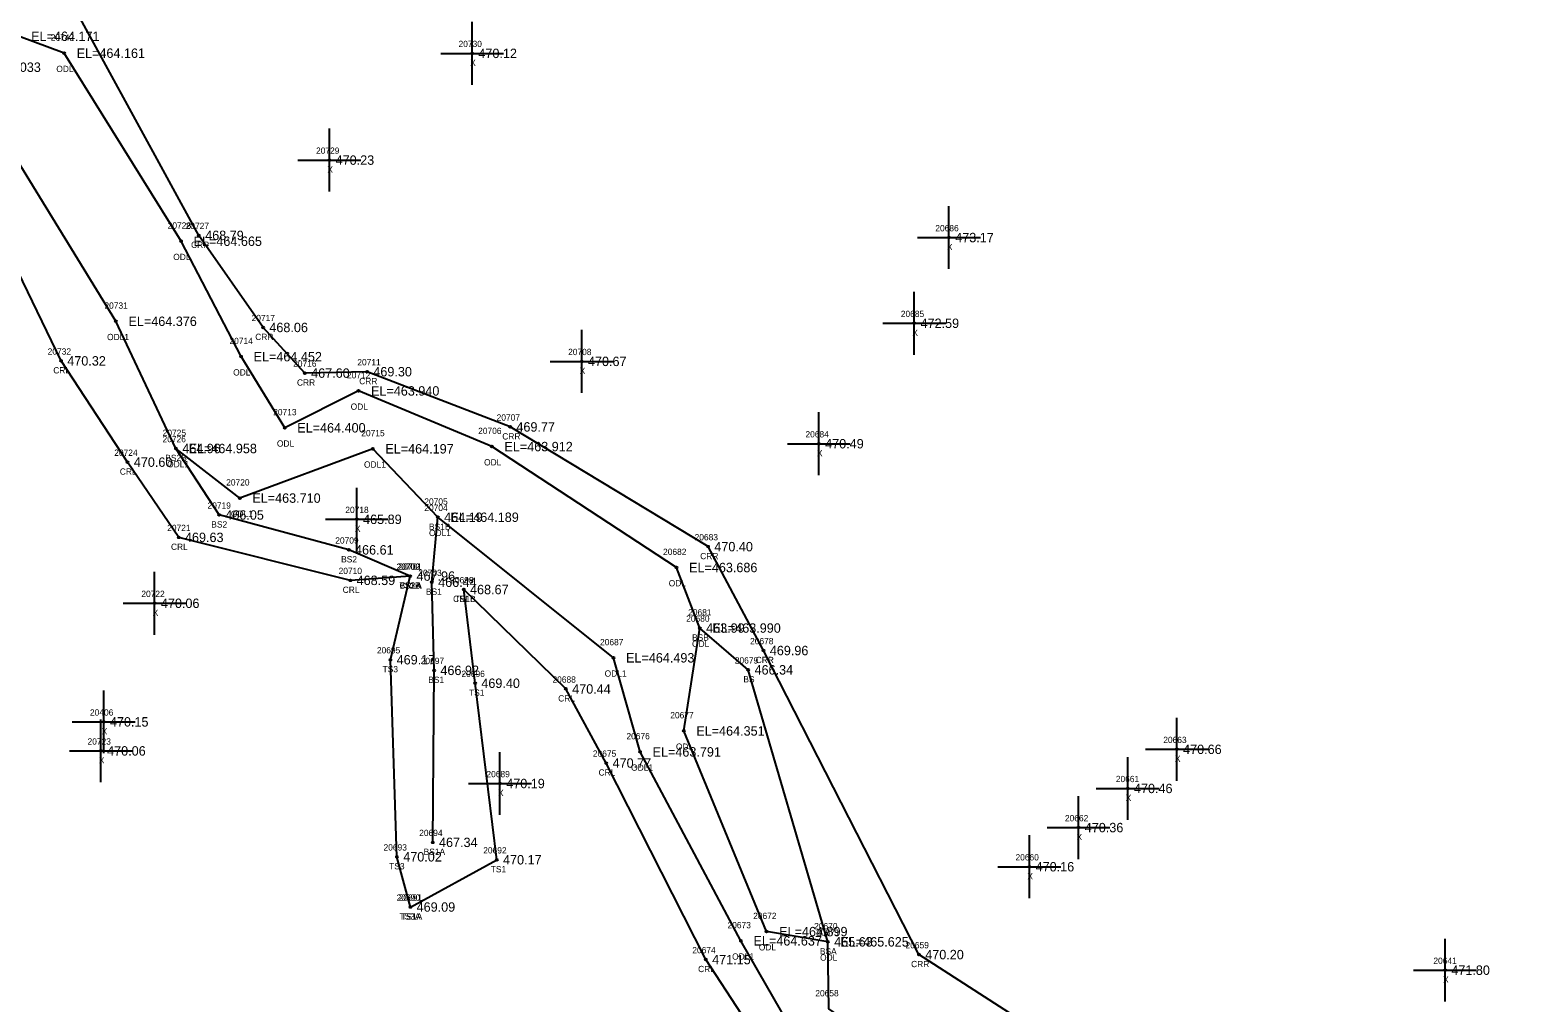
# Model space of a CAD drawing. Extents: x 1741010 to 1742139, y 749382 to 750625.
# Drawn here: x 1741616.4 to 1741856.4, y 749886.5 to 750041.3 of the extents above; entities that cross this region are included whole.
import ezdxf

# ---------------------------------------------------------------- set-up
doc = ezdxf.new("R2010")
doc.units = 0
for name, color, linetype in [('RD_DTM_BkLn2', 7, 'Continuous'), ('RD_DTM_BkLn_txCode', 7, 'Continuous'), ('RD_EX_H2O', 7, 'Continuous'), ('RD_EX_H2O_txCode', 7, 'Continuous'), ('RD_EX_Misc', 7, 'Continuous'), ('RD_EX_Misc_txCode', 7, 'Continuous'), ('RD_EX_TX_H2O_ELEV', 7, 'Continuous'), ('RD_EX_TX_Misc_ELEV', 7, 'Continuous'), ('RD_SMD_Locator', 7, 'Continuous')]:
    doc.layers.add(name, color=color, linetype=linetype)

msp = doc.modelspace()

# ---------------------------------------------------------------- linework, layer by layer
at = {"layer": 'RD_DTM_BkLn2'}
for points in [[(1741676.89, 749954.42), (1741667.11, 749958.59), (1741646.46, 749964.14), (1741639.61, 749974.72)], [(1741680.47, 749912.05), (1741680.7, 749939.42), (1741680.34, 749953.44), (1741681.29, 749963.78)], [(1741676.91, 749901.76), (1741674.78, 749909.75), (1741673.73, 749941.11), (1741676.89, 749954.42)], [(1741676.91, 749901.76), (1741690.66, 749909.28), (1741687.21, 749937.37), (1741685.41, 749952.28)], [(1741743.36, 749896.22), (1741730.69, 749939.5), (1741722.99, 749946.15)]]:
    msp.add_lwpolyline(points, dxfattribs=at)
at = {"layer": 'RD_EX_H2O'}
for points in [[(1742009.73, 749699.92), (1741998.41, 749723.73), (1741963.19, 749743.52), (1741899.78, 749744.87), (1741875.61, 749759.72), (1741846.8, 749796.06), (1741820.86, 749838.72), (1741812.23, 749854.24), (1741798.02, 749868.34), (1741757.86, 749894.19), (1741733.12, 749942.57), (1741724.29, 749959.1), (1741692.79, 749978.15), (1741670.02, 749986.94), (1741660.12, 749986.72), (1741653.47, 749993.98), (1741643.26, 750008.63), (1741623.07, 750045.53)], [(1741979.95, 749694.15), (1741975.81, 749711.2), (1741958.44, 749721.88), (1741894.61, 749726.87), (1741877.76, 749724.44), (1741850.91, 749736.65), (1741828.26, 749780.7), (1741797.14, 749817.35), (1741808.22, 749831.81), (1741810.09, 749840.16), (1741785.92, 749848.46), (1741738.7, 749880.42), (1741729.53, 749896.38), (1741713.46, 749926.44), (1741709.24, 749941.41), (1741681.29, 749963.78), (1741670.93, 749974.67), (1741649.76, 749966.83), (1741639.61, 749974.72), (1741630.05, 749994.96), (1741605.22, 750035.39), (1741604.28, 750042.48)], [(1741997.88, 749696.99), (1741991.24, 749718.21), (1741959.63, 749735.24), (1741894.45, 749731.15), (1741878.5, 749730.08), (1741867.7, 749749.38), (1741830.02, 749787.48), (1741810.47, 749825.74), (1741816.53, 749831.94), (1741813.36, 749842.06), (1741786.5, 749855.75), (1741743.5, 749885.54), (1741743.36, 749896.22), (1741733.61, 749897.85), (1741720.42, 749929.78), (1741722.99, 749946.15), (1741719.27, 749955.78), (1741689.88, 749975.02), (1741668.65, 749983.88), (1741656.91, 749978.01), (1741649.96, 749989.33), (1741640.41, 750007.7), (1741621.8, 750037.62), (1741614.56, 750040.31)], [(1741676.89, 749954.42), (1741667.36, 749953.74), (1741640.04, 749960.58), (1741631.9, 749972.55), (1741621.31, 749988.66), (1741602.28, 750027.97)], [(1741846.63, 749736.99), (1741818.31, 749776.35), (1741788.49, 749817.31), (1741765.98, 749840.78), (1741735.27, 749875.99), (1741723.94, 749893.4), (1741708.1, 749924.67), (1741701.67, 749936.46), (1741685.41, 749952.28)]]:
    msp.add_lwpolyline(points, dxfattribs=at)
at = {"layer": 'RD_EX_Misc'}
for p, q in [((1741686.74, 750032.59), (1741686.74, 750042.59)), ((1741681.74, 750037.59), (1741691.74, 750037.59)), ((1741664.02, 750015.61), (1741664.02, 750025.61)), ((1741659.02, 750020.61), (1741669.02, 750020.61)), ((1741762.63, 750003.28), (1741762.63, 750013.28)), ((1741757.63, 750008.28), (1741767.63, 750008.28)), ((1741757.11, 749989.64), (1741757.11, 749999.64)), ((1741704.18, 749983.58), (1741704.18, 749993.58)), ((1741752.11, 749994.64), (1741762.11, 749994.64)), ((1741699.18, 749988.58), (1741709.18, 749988.58)), ((1741741.93, 749970.48), (1741741.93, 749980.48)), ((1741736.93, 749975.48), (1741746.93, 749975.48)), ((1741668.39, 749958.45), (1741668.39, 749968.45)), ((1741663.39, 749963.45), (1741673.39, 749963.45)), ((1741636.21, 749945.09), (1741636.21, 749955.09)), ((1741631.21, 749950.09), (1741641.21, 749950.09)), ((1741628.1, 749926.22), (1741628.1, 749936.22)), ((1741623.1, 749931.22), (1741633.1, 749931.22)), ((1741627.65, 749921.6), (1741627.65, 749931.6)), ((1741798.9, 749921.85), (1741798.9, 749931.85)), ((1741622.65, 749926.6), (1741632.65, 749926.6)), ((1741691.17, 749916.41), (1741691.17, 749926.41)), ((1741793.9, 749926.85), (1741803.9, 749926.85)), ((1741791.08, 749915.63), (1741791.08, 749925.63)), ((1741686.17, 749921.41), (1741696.17, 749921.41)), ((1741783.25, 749909.4), (1741783.25, 749919.4)), ((1741786.08, 749920.63), (1741796.08, 749920.63)), ((1741778.25, 749914.4), (1741788.25, 749914.4)), ((1741775.43, 749903.17), (1741775.43, 749913.17)), ((1741770.43, 749908.17), (1741780.43, 749908.17)), ((1741841.59, 749886.71), (1741841.59, 749896.71)), ((1741836.59, 749891.71), (1741846.59, 749891.71))]:
    msp.add_line(p, q, dxfattribs=at)
at = {"layer": 'RD_SMD_Locator'}
for centre in [(1741621.8, 750037.62), (1741686.74, 750037.59), (1741664.02, 750020.61), (1741640.41, 750007.7), (1741643.26, 750008.63), (1741762.63, 750008.28), (1741630.05, 749994.96), (1741653.47, 749993.98), (1741757.11, 749994.64), (1741621.31, 749988.66), (1741649.96, 749989.33), (1741704.18, 749988.58), (1741660.12, 749986.72), (1741670.02, 749986.94), (1741668.65, 749983.88), (1741656.91, 749978.01), (1741692.79, 749978.15), (1741639.61, 749974.72), (1741639.61, 749974.72), (1741670.93, 749974.67), (1741689.88, 749975.02), (1741741.93, 749975.48), (1741631.9, 749972.55), (1741649.76, 749966.83), (1741646.46, 749964.14), (1741668.39, 749963.45), (1741681.29, 749963.78), (1741681.29, 749963.78), (1741640.04, 749960.58), (1741667.11, 749958.59), (1741724.29, 749959.1), (1741719.27, 749955.78), (1741667.36, 749953.74), (1741676.89, 749954.42), (1741676.89, 749954.42), (1741676.89, 749954.42), (1741680.34, 749953.44), (1741685.41, 749952.28), (1741685.41, 749952.28), (1741636.21, 749950.09), (1741722.99, 749946.15), (1741722.99, 749946.15), (1741673.73, 749941.11), (1741709.24, 749941.41), (1741733.12, 749942.57), (1741680.7, 749939.42), (1741730.69, 749939.5), (1741687.21, 749937.37), (1741701.67, 749936.46), (1741628.1, 749931.22), (1741720.42, 749929.78), (1741627.65, 749926.6), (1741713.46, 749926.44), (1741798.9, 749926.85), (1741708.1, 749924.67), (1741691.17, 749921.41), (1741791.08, 749920.63), (1741783.25, 749914.4), (1741680.47, 749912.05), (1741674.78, 749909.75), (1741690.66, 749909.28), (1741775.43, 749908.17), (1741676.91, 749901.76), (1741676.91, 749901.76), (1741733.61, 749897.85), (1741729.53, 749896.38), (1741743.36, 749896.22), (1741743.36, 749896.22), (1741723.94, 749893.4), (1741757.86, 749894.19), (1741841.59, 749891.71)]:
    msp.add_circle(centre, 0.15, dxfattribs=at)

# ---------------------------------------------------------------- texts
at = {"layer": 'RD_DTM_BkLn_txCode'}
for s, p in [('20726', (1741637.47, 749975.72)), ('BS2B', (1741637.91, 749972.72)), ('20719', (1741644.63, 749965.14)), ('20704', (1741679.13, 749964.78)), ('BS2', (1741645.23, 749962.14)), ('BS1B', (1741679.87, 749961.78)), ('20709', (1741664.96, 749959.59)), ('BS2', (1741665.89, 749956.59)), ('20702', (1741674.74, 749955.42)), ('20701', (1741675.02, 749955.42)), ('20703', (1741678.18, 749954.44)), ('TS3B', (1741675.18, 749952.42)), ('BS2A', (1741675.18, 749952.42)), ('BS1', (1741679.39, 749951.44)), ('20698', (1741683.26, 749953.28)), ('TS1B', (1741683.97, 749950.28)), ('20680', (1741720.81, 749947.15)), ('20695', (1741671.59, 749942.11)), ('BSB', (1741721.74, 749944.15)), ('20697', (1741678.56, 749940.42)), ('20679', (1741728.55, 749940.5)), ('TS3', (1741672.49, 749939.11)), ('BS1', (1741679.76, 749937.42)), ('20696', (1741685.05, 749938.37)), ('BS', (1741729.91, 749937.5)), ('TS1', (1741686.25, 749935.37)), ('20694', (1741678.32, 749913.05)), ('20693', (1741672.64, 749910.75)), ('BS1A', (1741679.03, 749910.05)), ('20692', (1741688.51, 749910.28)), ('TS3', (1741673.54, 749907.75)), ('TS1', (1741689.7, 749907.28)), ('20690', (1741674.73, 749902.76)), ('20691', (1741675.05, 749902.76)), ('TS3A', (1741675.18, 749899.76)), ('TS1A', (1741675.46, 749899.76)), ('20671', (1741741.5, 749897.22)), ('BSA', (1741742.09, 749894.22))]:
    msp.add_text(s, height=1, dxfattribs=at).set_placement(p)
at = {"layer": 'RD_EX_H2O_txCode'}
for s, p in [('20742', (1741619.68, 750039.62)), ('ODL', (1741620.56, 750034.62)), ('20728', (1741638.29, 750009.7)), ('20727', (1741641.14, 750009.63)), ('CRR', (1741642.01, 750006.63)), ('ODL', (1741639.17, 750004.7)), ('20731', (1741628.22, 749996.96)), ('20717', (1741651.64, 749994.98)), ('ODL1', (1741628.64, 749991.96)), ('20714', (1741648.12, 749991.33)), ('CRR', (1741652.22, 749991.98)), ('20732', (1741619.19, 749989.66)), ('20716', (1741658.26, 749987.72)), ('20711', (1741668.47, 749987.94)), ('CRL', (1741620.08, 749986.66)), ('ODL', (1741648.71, 749986.33)), ('20712', (1741666.82, 749985.88)), ('CRR', (1741658.86, 749984.72)), ('CRR', (1741668.77, 749984.94)), ('ODL', (1741667.41, 749980.88)), ('20713', (1741655.08, 749980.01)), ('20707', (1741690.64, 749979.15)), ('20725', (1741637.49, 749976.72)), ('20715', (1741669.1, 749976.67)), ('20706', (1741687.7, 749977.02)), ('CRR', (1741691.54, 749976.15)), ('20724', (1741629.78, 749973.55)), ('ODL', (1741655.67, 749975.01)), ('ODL1', (1741638.2, 749971.72)), ('ODL1', (1741669.53, 749971.67)), ('ODL', (1741688.64, 749972.02)), ('CRL', (1741630.67, 749970.55)), ('20720', (1741647.6, 749968.83)), ('ODL1', (1741648.35, 749963.83)), ('20705', (1741679.13, 749965.78)), ('20721', (1741638.21, 749961.58)), ('ODL1', (1741679.88, 749960.78)), ('20683', (1741722.15, 749960.1)), ('CRL', (1741638.81, 749958.58)), ('20682', (1741717.13, 749957.78)), ('CRR', (1741723.04, 749957.1)), ('20710', (1741665.49, 749954.74)), ('20700', (1741674.7, 749955.42)), ('CRL', (1741666.14, 749951.74)), ('CRLA', (1741675.18, 749952.42)), ('20699', (1741683.26, 749953.28)), ('ODL', (1741718.03, 749952.78)), ('CRLB', (1741683.71, 749950.28)), ('20681', (1741721.13, 749948.15)), ('20687', (1741707.1, 749943.41)), ('ODL', (1741721.74, 749943.15)), ('20678', (1741730.98, 749943.57)), ('CRR', (1741731.87, 749940.57)), ('20688', (1741699.53, 749937.46)), ('ODL1', (1741707.83, 749938.41)), ('CRL', (1741700.44, 749934.46)), ('20677', (1741718.28, 749931.78)), ('20676', (1741711.3, 749928.44)), ('20675', (1741705.96, 749925.67)), ('ODL', (1741719.18, 749926.78)), ('CRL', (1741706.87, 749922.67)), ('ODL1', (1741712.05, 749923.44)), ('20672', (1741731.47, 749899.85)), ('20673', (1741727.39, 749898.38)), ('20670', (1741741.18, 749898.22)), ('20674', (1741721.79, 749894.4)), ('ODL', (1741732.37, 749894.85)), ('20659', (1741755.72, 749895.19)), ('ODL1', (1741728.12, 749893.38)), ('ODL', (1741742.12, 749893.22)), ('CRR', (1741756.61, 749892.19)), ('CRL', (1741722.71, 749891.4)), ('20658', (1741741.36, 749887.54))]:
    msp.add_text(s, height=1, dxfattribs=at).set_placement(p)
at = {"layer": 'RD_EX_Misc_txCode'}
for s, p in [('20730', (1741684.58, 750038.59)), ('X', (1741686.43, 750035.59)), ('20729', (1741661.9, 750021.61)), ('X', (1741663.7, 750018.61)), ('20686', (1741760.46, 750009.28)), ('X', (1741762.31, 750006.28)), ('20685', (1741754.97, 749995.64)), ('X', (1741756.8, 749992.64)), ('20708', (1741702.02, 749989.58)), ('X', (1741703.86, 749986.58)), ('20684', (1741739.79, 749976.48)), ('X', (1741741.62, 749973.48)), ('20718', (1741666.56, 749964.45)), ('X', (1741668.08, 749961.45)), ('20722', (1741634.1, 749951.09)), ('X', (1741635.9, 749948.09)), ('20406', (1741625.92, 749932.22)), ('20723', (1741625.53, 749927.6)), ('X', (1741627.78, 749929.22)), ('20663', (1741796.74, 749927.85)), ('X', (1741627.33, 749924.6)), ('X', (1741798.59, 749924.85)), ('20689', (1741689.02, 749922.41)), ('20661', (1741789.19, 749921.63)), ('X', (1741690.85, 749919.41)), ('X', (1741790.76, 749918.63)), ('20662', (1741781.09, 749915.4)), ('X', (1741782.94, 749912.4)), ('20660', (1741773.22, 749909.17)), ('X', (1741775.11, 749906.17)), ('20641', (1741839.73, 749892.71)), ('X', (1741841.28, 749889.71))]:
    msp.add_text(s, height=1, dxfattribs=at).set_placement(p)
at = {"layer": 'RD_EX_TX_H2O_ELEV'}
for s, p in [('EL=464.171', (1741616.56, 750039.56)), ('EL=464.161', (1741623.8, 750036.87)), ('EL=464.033', (1741607.22, 750034.64)), ('EL=464.665', (1741642.41, 750006.95)), ('468.79', (1741644.26, 750007.88)), ('EL=464.376', (1741632.05, 749994.21)), ('468.06', (1741654.47, 749993.23)), ('470.32', (1741622.31, 749987.91)), ('EL=464.452', (1741651.96, 749988.58)), ('467.60', (1741661.12, 749985.97)), ('469.30', (1741671.02, 749986.19)), ('EL=463.940', (1741670.65, 749983.13)), ('469.77', (1741693.79, 749977.4)), ('EL=464.400', (1741658.91, 749977.26)), ('EL=464.958', (1741641.61, 749973.97)), ('EL=464.197', (1741672.93, 749973.92)), ('EL=463.912', (1741691.88, 749974.27)), ('470.60', (1741632.9, 749971.8)), ('EL=463.710', (1741651.76, 749966.08)), ('EL=464.189', (1741683.29, 749963.03)), ('469.63', (1741641.04, 749959.83)), ('470.40', (1741725.29, 749958.35)), ('467.96', (1741677.89, 749953.67)), ('EL=463.686', (1741721.27, 749955.03)), ('468.59', (1741668.36, 749952.99)), ('468.67', (1741686.41, 749951.53)), ('EL=463.990', (1741724.99, 749945.4)), ('469.96', (1741734.12, 749941.82)), ('EL=464.493', (1741711.24, 749940.66)), ('470.44', (1741702.67, 749935.71)), ('EL=464.351', (1741722.42, 749929.03)), ('EL=463.791', (1741715.46, 749925.69)), ('470.77', (1741709.1, 749923.92)), ('EL=464.899', (1741735.61, 749897.1)), ('EL=464.637', (1741731.53, 749895.63)), ('EL=465.625', (1741745.36, 749895.47)), ('470.20', (1741758.86, 749893.44)), ('471.15', (1741724.94, 749892.65))]:
    msp.add_text(s, height=1.5, dxfattribs=at).set_placement(p)
at = {"layer": 'RD_EX_TX_Misc_ELEV'}
for s, p in [('470.12', (1741687.74, 750036.84)), ('470.23', (1741665.02, 750019.86)), ('473.17', (1741763.63, 750007.53)), ('472.59', (1741758.11, 749993.89)), ('470.67', (1741705.18, 749987.83)), ('464.96', (1741640.61, 749973.97)), ('470.49', (1741742.93, 749974.73)), ('466.05', (1741647.46, 749963.39)), ('464.19', (1741682.29, 749963.03)), ('465.89', (1741669.39, 749962.7)), ('466.61', (1741668.11, 749957.84)), ('467.96', (1741677.89, 749953.67)), ('467.96', (1741677.89, 749953.67)), ('466.44', (1741681.34, 749952.69)), ('468.67', (1741686.41, 749951.53)), ('470.06', (1741637.21, 749949.34)), ('463.99', (1741723.99, 749945.4)), ('469.17', (1741674.73, 749940.36)), ('466.92', (1741681.7, 749938.67)), ('469.40', (1741688.21, 749936.62)), ('466.34', (1741731.69, 749938.75)), ('470.15', (1741629.1, 749930.47)), ('470.06', (1741628.65, 749925.85)), ('470.66', (1741799.9, 749926.1)), ('470.19', (1741692.17, 749920.66)), ('470.46', (1741792.08, 749919.88)), ('470.36', (1741784.25, 749913.65)), ('467.34', (1741681.47, 749911.3)), ('470.02', (1741675.78, 749909)), ('470.17', (1741691.66, 749908.53)), ('470.16', (1741776.43, 749907.42)), ('469.09', (1741677.91, 749901.01)), ('469.09', (1741677.91, 749901.01)), ('465.63', (1741744.36, 749895.47)), ('471.80', (1741842.59, 749890.96))]:
    msp.add_text(s, height=1.5, dxfattribs=at).set_placement(p)

doc.saveas('drawing.dxf')
